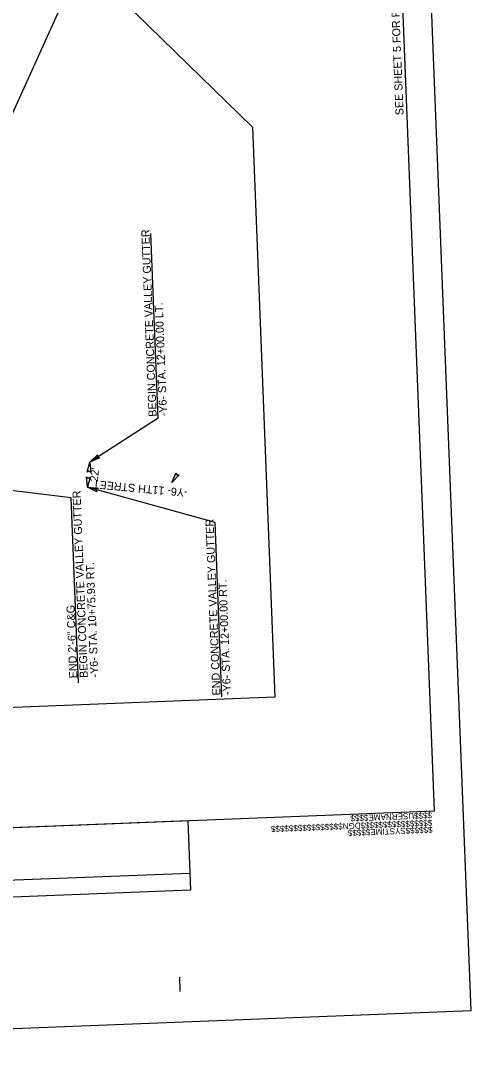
# Model space of a CAD drawing. Extents: x 1627811 to 1628977, y 762656 to 764629.
# Drawn here: x 1628584 to 1628977, y 762656 to 763561 of the extents above; entities that cross this region are included whole.
import ezdxf

# ---------------------------------------------------------------- set-up
doc = ezdxf.new("R2010")
doc.units = 0
for name, color, linetype in [('Default', 7, 'Continuous'), ('Prop Dimension', 7, 'Continuous'), ('Prop Dimension Text', 7, 'Continuous'), ('Prop DSN Text', 7, 'Continuous'), ('Prop Terminator CELL', 7, 'Continuous'), ('Sheet Block Revision CELL', 7, 'Continuous'), ('Sheet Block System Information CELL', 7, 'Continuous'), ('Sheet Clip Boundary CELL', 7, 'Continuous'), ('Sheet Plan And Profile CELL', 7, 'Continuous'), ('Sheet Plot Border Outside CELL', 7, 'Continuous')]:
    doc.layers.add(name, color=color, linetype=linetype)

msp = doc.modelspace()

# ---------------------------------------------------------------- linework, layer by layer
at = {"layer": 'Prop Dimension'}
for p, q in [((1628703.99, 763215.43), (1628697.65, 763376.25)), ((1628703.99, 763215.43), (1628644.5, 763177.04)), ((1628628.35, 763145.87), (1628519.11, 763159.17)), ((1628753.52, 763124.41), (1628642.45, 763155.14)), ((1628634.7, 762984.83), (1628628.35, 763145.87)), ((1628759.51, 762972.58), (1628753.52, 763124.41))]:
    msp.add_line(p, q, dxfattribs=at)
at = {"layer": 'Prop Terminator CELL'}
for points in [[(1628652.9, 763180.62), (1628644.5, 763177.04), (1628651.24, 763183.29), (1628651.14, 763181.33)], [(1628642.12, 763168.23), (1628644.5, 763177.04), (1628645.25, 763167.88), (1628643.77, 763169.18)], [(1628722.21, 763165.95), (1628715.92, 763159.32), (1628719.61, 763167.74), (1628720.31, 763165.89)], [(1628644.83, 763163.96), (1628642.45, 763155.14), (1628641.7, 763164.3), (1628643.19, 763163.01)], [(1628650.71, 763151.25), (1628642.45, 763155.14), (1628651.6, 763154.27), (1628650.07, 763153.03)]]:
    msp.add_lwpolyline(points, close=True, dxfattribs=at)
at = {"layer": 'Sheet Block Revision CELL'}
msp.add_line((1628731.74, 762818.75), (1627941.71, 762787.59), dxfattribs=at)
msp.add_lwpolyline([(1628732.32, 762804.21), (1627942.28, 762773.06), (1627939.89, 762833.56), (1628729.93, 762864.71)], close=True, dxfattribs=at)
at = {"layer": 'Sheet Block System Information CELL'}
msp.add_line((1628944.76, 762873.18), (1628944.76, 762873.18), dxfattribs=at)
at = {"layer": 'Sheet Clip Boundary CELL'}
msp.add_lwpolyline([(1628080.25, 762943.5), (1628060.66, 763440.11), (1628567.89, 763460.11), (1628623.39, 763582.83), (1628623.86, 763610.17), (1628631.44, 763609.98), (1628639.19, 763612.32), (1628786.08, 763468.72), (1628805.66, 762972.11)], close=True, dxfattribs=at)
at = {"layer": 'Sheet Plan And Profile CELL'}
for p, q in [((1628944.76, 762873.18), (1628944.76, 762873.18)), ((1628944.76, 762873.18), (1628944.76, 762873.18)), ((1628944.76, 762873.18), (1628944.76, 762873.18)), ((1628944.76, 762873.18), (1628944.76, 762873.18)), ((1628944.76, 762873.18), (1628944.76, 762873.18)), ((1628723.29, 762715.83), (1628722.8, 762728.32))]:
    msp.add_line(p, q, dxfattribs=at)
msp.add_lwpolyline([(1627836.47, 764330.65), (1627895.58, 762831.81), (1628944.76, 762873.18), (1628885.66, 764372.02)], close=True, dxfattribs=at)
at = {"layer": 'Sheet Plot Border Outside CELL'}
msp.add_lwpolyline([(1628976.64, 762699.3), (1628909.65, 764397.98), (1627810.51, 764354.64), (1627877.49, 762655.96)], close=True, dxfattribs=at)

# ---------------------------------------------------------------- texts
at = {"layer": 'Default'}
msp.add_text('SEE SHEET 5 FOR PLAN VIEW', height=7, rotation=92.25819, dxfattribs=at).set_placement((1628917.76, 763479.38))
at = {"layer": 'Prop Dimension Text'}
for s, rotation, p in [('BEGIN CONCRETE VALLEY GUTTER', 92.25819, (1628702.71, 763216.7)), ('-Y6- STA. 12+00.00 LT.', 92.25819, (1628711.88, 763217.06)), ("22'", 84.66319, (1628651.46, 763159.72)), ('BEGIN CONCRETE VALLEY GUTTER', 92.25819, (1628642.8, 762989.16)), ('END CONCRETE VALLEY GUTTER', 92.25819, (1628758.24, 762973.86)), ('-Y6- STA. 10+75.93 RT.', 92.25819, (1628651.97, 762989.52)), ('-Y6- STA. 12+00.00 RT.', 92.25819, (1628767.41, 762974.22)), ('END 2\'-6" C&G', 92.25819, (1628633.63, 762988.79))]:
    msp.add_text(s, height=7, rotation=rotation, dxfattribs=at).set_placement(p)
at = {"layer": 'Prop DSN Text'}
msp.add_text('-Y6- 11TH STREET', height=7, rotation=174.66319, dxfattribs=at).set_placement((1628729.92, 763153.57))
at = {"layer": 'Sheet Block System Information CELL'}
for s, p in [('$$$$USERNAME$$$$', (1628942.43, 762872.02)), ('$$$$$$$$$$$$$$$$DGN$$$$$$$$$$$$$$$$', (1628942.7, 762865.45)), ('$$$$$$SYSTIME$$$$$', (1628942.94, 762859.4))]:
    msp.add_text(s, height=5.25, rotation=182.25819, dxfattribs=at).set_placement(p)

doc.saveas('drawing.dxf')
